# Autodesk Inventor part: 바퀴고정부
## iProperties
Company: 한국ATC센터
Created: 2015-05
Part Number: 바퀴고정부
Document SubType Name: 모델링
Designer: KYOUNG IL JANG
Vendor: CBT Solutions
Author: KYOUNG IL JANG
Comments: 파생
